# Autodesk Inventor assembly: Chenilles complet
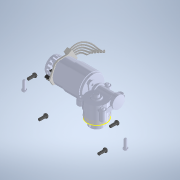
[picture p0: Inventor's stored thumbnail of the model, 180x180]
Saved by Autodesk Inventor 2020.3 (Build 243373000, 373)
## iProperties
Created: 2018-09
Part Number: Chenilles complet
Document SubType Name: Assembly
Designer: ficho
Mass: 54.5723 g
Surface Area: 606.453 cm^2
Volume: 50.8653 cm^3
Density: 1.07288 g/cm^3
Sending System: SolidWorks 2015
Last Author: adrien
Last Saved: 2019-01-14
Author: ficho
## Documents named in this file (4)
- D:\travail\année 2020-2021\2I2D\laveur de vitre\Lave vitre\4 Dossier Ressources\1 Modèles 3D Solidworks\Chenilles complet.iam
- D:\travail\année 2020-2021\2I2D\laveur de vitre\Lave vitre\4 Dossier Ressources\1 Modèles 3D Solidworks\Vis 3x12.ipt
- D:\travail\année 2020-2021\2I2D\laveur de vitre\Lave vitre\4 Dossier Ressources\1 Modèles 3D Solidworks\Assemblage Réducteur.iam
- D:\travail\année 2020-2021\2I2D\laveur de vitre\Lave vitre\4 Dossier Ressources\1 Modèles 3D Solidworks\Moteur circuit imprimé.iam
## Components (5 placed, 3 different names)
1. Vis 3x12:1
2. Vis 3x12:2
3. Vis 3x12:3
4. Moteur circuit imprimé:1 [sub-assembly] — Placage:2
5. Assemblage Réducteur:1 [sub-assembly] — Placage:2
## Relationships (1: Mate 1)
- Placage:2 [Mate]: Moteur circuit imprimé:1 ↔ Assemblage Réducteur:1
